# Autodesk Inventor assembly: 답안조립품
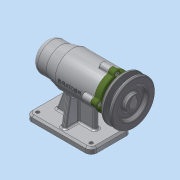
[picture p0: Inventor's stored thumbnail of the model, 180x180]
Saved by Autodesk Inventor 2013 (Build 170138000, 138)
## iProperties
Created: 2019-07
Part Number: 답안조립품
Document SubType Name: Assembly
Designer: Administrator
Author: Administrator
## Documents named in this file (12)
- C:\Users\Administrator\Desktop\490704V1022\답안조립품.iam
- C:\Users\Administrator\Desktop\490704V1022\1-본체.ipt
- C:\Users\Administrator\Desktop\490704V1022\베어링 51202.ipt
- C:\Users\Administrator\Desktop\490704V1022\어댑터슬리브.ipt
- C:\Users\Administrator\Desktop\490704V1022\베어링 6004.ipt
- C:\Users\Administrator\Desktop\490704V1022\축.ipt
- C:\Users\Administrator\Desktop\490704V1022\볼트 M4.ipt
- C:\Users\Administrator\Desktop\490704V1022\커버.ipt
- C:\Users\Administrator\Desktop\490704V1022\오일 실.ipt
- C:\Users\Administrator\Desktop\490704V1022\키 5 x 5 x 16.ipt
- C:\Users\Administrator\Desktop\490704V1022\V벨트풀리.ipt
- C:\Users\Administrator\Desktop\490704V1022\멈춤나사 M3.ipt
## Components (2 placed, 2 different names)
1. 1-본체:1
2. V벨트풀리:1 — 각도:2
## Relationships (1: Angle 1)
- 각도:2 [Angle]: V벨트풀리:1
